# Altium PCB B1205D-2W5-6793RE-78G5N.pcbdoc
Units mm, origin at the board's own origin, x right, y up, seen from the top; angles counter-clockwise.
Board outline 65 x 30 mm, 2 copper layers (Top Layer, Bottom Layer), stack 0.78 mm thick; 15 components, 11 nets, 42 pads, 94 vias.
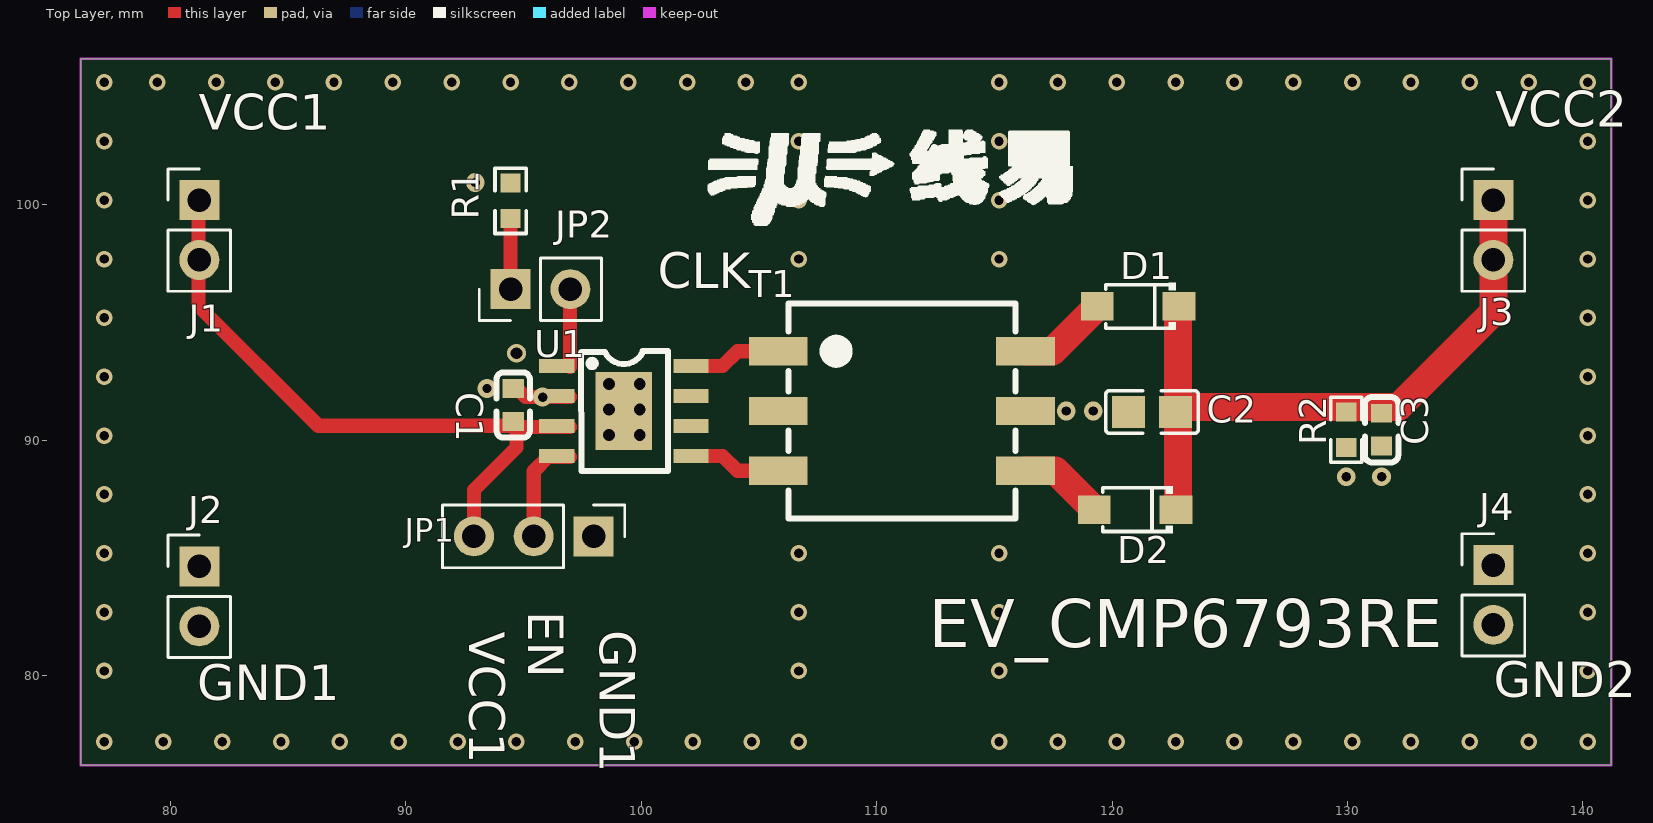
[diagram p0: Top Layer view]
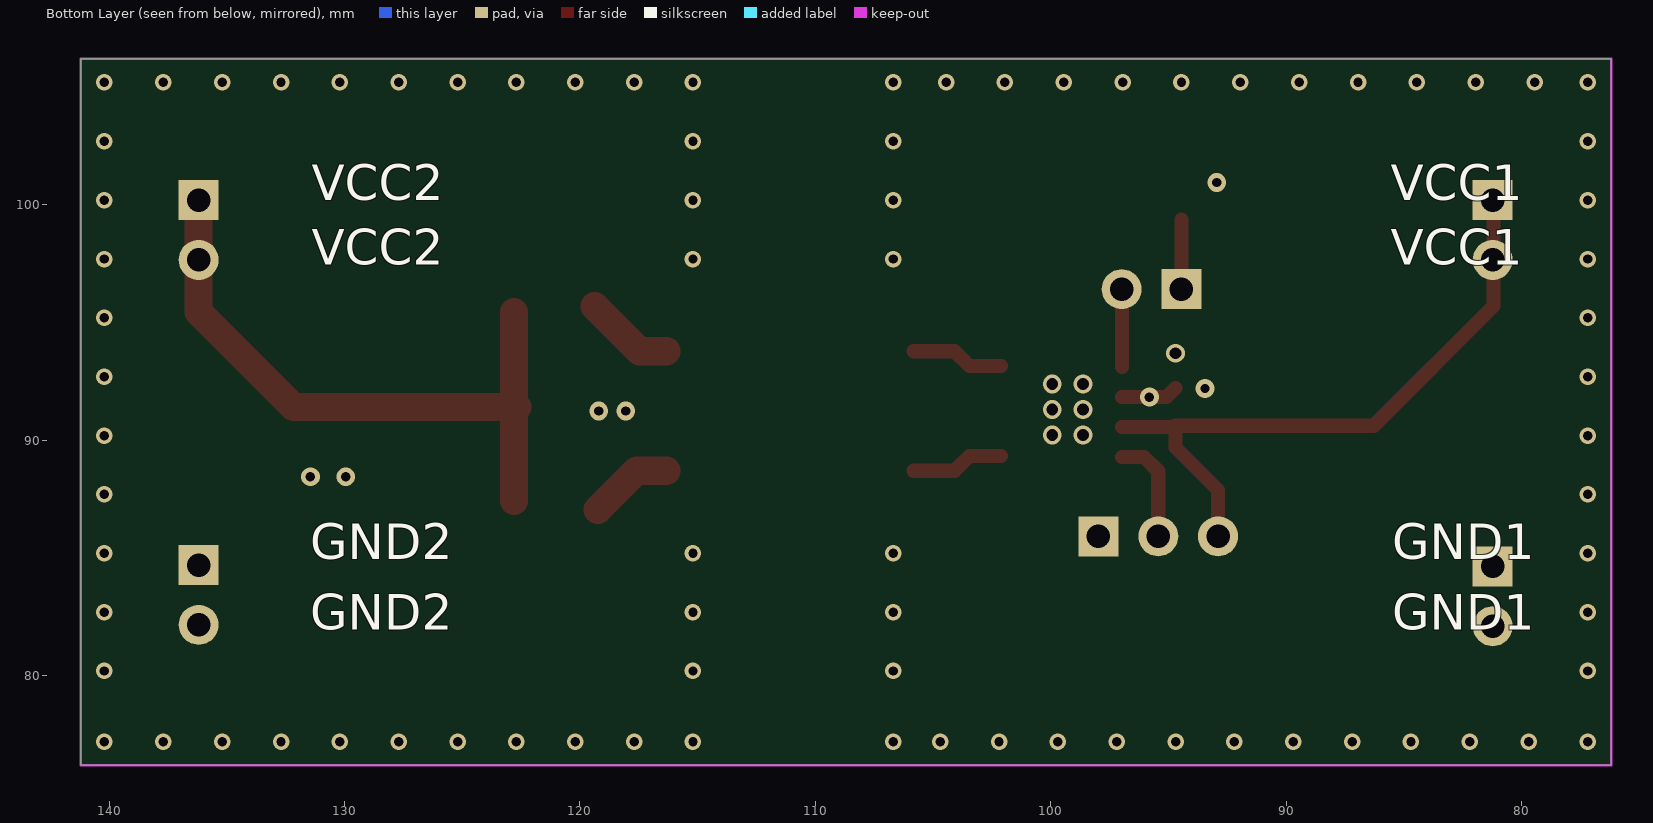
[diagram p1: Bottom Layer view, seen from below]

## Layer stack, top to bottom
Top Solder Mask Layer: solder mask 0.01, Dk 0
Top Layer: signal copper 0.035
dielectric 1: surface 0.71, FR4, Dk 4.5
Bottom Layer: signal copper 0.035
Bottom Solder Mask Layer: solder mask 0.01, Dk 0

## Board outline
76.2,106.2 141.2,106.2 141.2,76.2 76.2,76.2

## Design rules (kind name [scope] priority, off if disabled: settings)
BoardOutlineClearance safeClearance [All] p0: genericclearance=0.254 ignorepadtopadclearanceinfootprint=FALSE except(0: Arc-SplitContinuation Track-SplitContinuation SMDPad-SplitContinuation THPad-SplitContinuation Via-SplitContinuation Fill-SplitContinuation Poly-SplitContinuation Region-SplitContinuation Text-SplitContinuation)
BoardOutlineClearance Plane_innerPlane [All] p0: genericclearance=0.254 ignorepadtopadclearanceinfootprint=FALSE except(0: Arc-SplitContinuation Track-SplitContinuation SMDPad-SplitContinuation THPad-SplitContinuation Via-SplitContinuation Fill-SplitContinuation Poly-SplitContinuation Region-SplitContinuation Text-SplitContinuation)
BoardOutlineClearance Copper_CopperRegion [All] p0: genericclearance=0.254 ignorepadtopadclearanceinfootprint=FALSE except(0: Arc-SplitContinuation Track-SplitContinuation SMDPad-SplitContinuation THPad-SplitContinuation Via-SplitContinuation Fill-SplitContinuation Poly-SplitContinuation Region-SplitContinuation Text-SplitContinuation)
BoardOutlineClearance Copper_CopperRegion1 [All] p0: genericclearance=0.254 ignorepadtopadclearanceinfootprint=FALSE except(0: Arc-SplitContinuation Track-SplitContinuation SMDPad-SplitContinuation THPad-SplitContinuation Via-SplitContinuation Fill-SplitContinuation Poly-SplitContinuation Region-SplitContinuation Text-SplitContinuation)
BoardOutlineClearance Copper_CopperRegion2 [All] p0: genericclearance=0.254 ignorepadtopadclearanceinfootprint=FALSE except(0: Arc-SplitContinuation Track-SplitContinuation SMDPad-SplitContinuation THPad-SplitContinuation Via-SplitContinuation Fill-SplitContinuation Poly-SplitContinuation Region-SplitContinuation Text-SplitContinuation)
BoardOutlineClearance Copper_CopperRegion3 [All] p0: genericclearance=0.254 ignorepadtopadclearanceinfootprint=FALSE except(0: Arc-SplitContinuation Track-SplitContinuation SMDPad-SplitContinuation THPad-SplitContinuation Via-SplitContinuation Fill-SplitContinuation Poly-SplitContinuation Region-SplitContinuation Text-SplitContinuation)
BoardOutlineClearance Copper_CopperRegion4 [All] p0: genericclearance=0.254 ignorepadtopadclearanceinfootprint=FALSE except(0: Arc-SplitContinuation Track-SplitContinuation SMDPad-SplitContinuation THPad-SplitContinuation Via-SplitContinuation Fill-SplitContinuation Poly-SplitContinuation Region-SplitContinuation Text-SplitContinuation)
BoardOutlineClearance otherClearance [All] p0: genericclearance=0.254 ignorepadtopadclearanceinfootprint=FALSE except(0: Arc-SplitContinuation Track-SplitContinuation SMDPad-SplitContinuation THPad-SplitContinuation Via-SplitContinuation Fill-SplitContinuation Poly-SplitContinuation Region-SplitContinuation Text-SplitContinuation)
Clearance safeClearance [All] p1: gap=0.178 ignorepadtopadclearanceinfootprint=FALSE
Clearance Plane_innerPlane [All] p1: gap=0.178 ignorepadtopadclearanceinfootprint=FALSE
Clearance Copper_CopperRegion [All] p1: gap=0.178 ignorepadtopadclearanceinfootprint=FALSE
Clearance Copper_CopperRegion1 [All] p1: gap=0.178 ignorepadtopadclearanceinfootprint=FALSE
Clearance Copper_CopperRegion2 [All] p1: gap=0.178 ignorepadtopadclearanceinfootprint=FALSE
Clearance Copper_CopperRegion3 [All] p1: gap=0.178 ignorepadtopadclearanceinfootprint=FALSE
Clearance Copper_CopperRegion4 [All] p1: gap=0.178 ignorepadtopadclearanceinfootprint=FALSE
Clearance otherClearance [All] p1: gap=0.178 ignorepadtopadclearanceinfootprint=FALSE
DiffPairsRouting differentialPair [All] p1: maxuncoupledlength=10 minlimit=6 maxlimit=Infinity mostfreqgap=6 toplayer_minwidth=5 toplayer_prefwidth=10 toplayer_maxwidth=100 bottomlayer_minwidth=5 bottomlayer_prefwidth=10 bottomlayer_maxwidth=100
PasteMaskExpansion Common [All] p1: expansion=0
PlaneConnect innerPlane [All] p1: planeconnectstyle=Relief reliefexpansion=0.508 reliefentries=4 reliefconductorwidth=0.254 reliefairgap=0.254
PolygonConnect CopperRegion [All] p1: connectstyle=Direct reliefentries=4 reliefconductorwidth=10 polygonreliefangle="90 Angle" airgapwidth=10
PolygonConnect CopperRegion1 [All] p1: connectstyle=Direct reliefentries=4 reliefconductorwidth=10 polygonreliefangle="90 Angle" airgapwidth=10
PolygonConnect CopperRegion2 [All] p1: connectstyle=Direct reliefentries=4 reliefconductorwidth=10 polygonreliefangle="90 Angle" airgapwidth=10
PolygonConnect CopperRegion3 [All] p1: connectstyle=Direct reliefentries=4 reliefconductorwidth=10 polygonreliefangle="90 Angle" airgapwidth=10
PolygonConnect CopperRegion4 [All] p1: connectstyle=Direct reliefentries=4 reliefconductorwidth=10 polygonreliefangle="90 Angle" airgapwidth=10
RoutingVias viaSize [All] p1: viastyle="Through Hole" holewidth=12 minholewidth=11.8 maxholewidth=236.2 width=12 minwidth=11.8 maxwidth=236.2
SolderMaskExpansion Common [All] p1: useseparateexpansions=TRUE expansion=0 expansionbottom=0
Width trackWidth [All] p1: maxlimit=100 minlimit=5 preferedwidth=10

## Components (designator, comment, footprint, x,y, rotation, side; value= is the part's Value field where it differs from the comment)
C1 "" C0603 94.564,91.498 r270 top
C2 "" C0805 121.7,91.2 r0 top
C3 "" C0603 131.45,90.45 r90 top
D1 "" SOD-123FL_L2.7-W1.8-LS3.8-RD 121.107,95.689 r180 top
D2 "" SOD-123FL_L2.7-W1.8-LS3.8-RD 120.98,87.053 r180 top
J1 "" Connector_PinHeader_2.54mm:PinHeader_1x02_P2.54mm_Vertical 81.229,100.2 r0 top
J2 "" Connector_PinHeader_2.54mm:PinHeader_1x02_P2.54mm_Vertical 81.229,84.64 r0 top
J3 "" Connector_PinHeader_2.54mm:PinHeader_1x02_P2.54mm_Vertical 136.2,100.2 r0 top
J4 "" Connector_PinHeader_2.54mm:PinHeader_1x02_P2.54mm_Vertical 136.2,84.7 r0 top
JP1 "Jumper_Jumper_3_Open" Connector_PinHeader_2.54mm:PinHeader_1x03_P2.54mm_Vertical 97.975,85.918 r270 top
JP2 "" Connector_PinHeader_2.54mm:PinHeader_1x02_P2.54mm_Vertical 94.45,96.418 r90 top
R1 "" R0603 94.45,100.168 r270 top
R2 "" R0603 129.95,90.45 r270 top
T1 "" SMD-6_L9.7-W8.9-P2.54-LS12.8-TL 111.074,91.244 r0 top
U1 "" ? 99.263,91.244 r270 top

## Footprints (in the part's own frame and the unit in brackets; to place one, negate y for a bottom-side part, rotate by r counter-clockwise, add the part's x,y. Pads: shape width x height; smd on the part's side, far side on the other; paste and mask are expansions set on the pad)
C0603 [mm]
  rect 0.8x0.9 smd: 1(-0.7,0) 2(0.7,0)
  silkscreen extent -1.39,-0.71 1.39,0.71
C0805 [mm]
  rect 1.41x1.35 smd: 1(-1,0) 2(1,0)
  silkscreen extent -1.96,-0.9 1.96,0.9
Connector_PinHeader_2.54mm:PinHeader_1x02_P2.54mm_Vertical [mm]
  rect 1.7x1.7 hole 1: 1(0,0)
  round 1.7 hole 1: 2(0,-2.54)
  silkscreen extent -1.33,-3.87 1.33,1.33
Connector_PinHeader_2.54mm:PinHeader_1x03_P2.54mm_Vertical [mm]
  rect 1.7x1.7 hole 1: 1(0,0)
  round 1.7 hole 1: 2(0,-2.54) 3(0,-5.08)
  silkscreen extent -1.33,-6.41 1.33,1.33
R0603 [mm]
  rect 0.806x0.864 smd: 1(-0.753,0) 2(0.753,0)
  silkscreen extent -1.39,-0.66 1.39,0.66
SMD-6_L9.7-W8.9-P2.54-LS12.8-TL [mm]
  rect 2.5x1.2 smd: 1(-5.25,2.54) 2(-5.25,0) 3(-5.25,-2.54) 4(5.25,-2.54) 5(5.25,0) 6(5.25,2.54)
  silkscreen extent -4.83,-4.57 4.83,4.57
SOD-123FL_L2.7-W1.8-LS3.8-RD [mm]
  rect 1.4x1.2 smd: 1(-1.735,0) 2(1.735,0)
  silkscreen extent -1.6,-1 1.38,1
? [mm]
  rect 0.6x1.5 smd: 1(-1.905,-2.85) 2(-0.635,-2.85) 3(0.635,-2.85) 4(1.905,-2.85) 5(1.905,2.85) 6(0.635,2.85) 7(-0.635,2.85) 8(-1.905,2.85)
  rect 3.3x2.4 smd: 9(0,0)
  silkscreen extent -2.55,-1.82 2.55,1.88

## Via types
v1: diameter 0.7, hole 0.4, Top Layer to Bottom Layer, 80 vias
v2: diameter 0.8, hole 0.5, Top Layer to Bottom Layer, 7 vias
v3: diameter 0.8, hole 0.4, Top Layer to Bottom Layer, 7 vias

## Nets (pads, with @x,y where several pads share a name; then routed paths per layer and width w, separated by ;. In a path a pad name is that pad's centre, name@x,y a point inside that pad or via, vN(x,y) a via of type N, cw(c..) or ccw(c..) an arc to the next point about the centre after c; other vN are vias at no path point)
$1N3479: JP2.1 R1.2 | length 2.9
  Top Layer w0.6: JP2.1 R1.2@94.45,99.368
$1N3481: T1.3 U1.5 | length 4
  Top Layer w0.599: U1.5 103.454,89.339 104.089,88.704 T1.3
$1N3522: T1.1 U1.8 | length 4
  Top Layer w0.599: U1.8 103.454,93.149 104.089,93.784 T1.1
$1N3537: D1.2 T1.6 | length 3.8
  Top Layer w1.199: T1.6 117.467,93.784 D1.2
$1N3538: D2.2 T1.4 | length 3.6
  Top Layer w1.199: T1.4 117.594,88.704 D2.2
CLK: JP2.2 U1.1 | length 3.3
  Top Layer w0.6: U1.1@96.97,93.105 JP2.2@96.97,96.398
EN: JP1.2 U1.4 | length 4.6
  Top Layer w0.6: JP1.2 95.435,88.685 96.045,89.295 U1.4@96.97,89.295
GND1: C1.1 J2.1 J2.2 JP1.1 R1.1 U1.2 U1.9 | length 2.4
  Top Layer w0.6: C1.1@94.7,92.218 95.083,91.835 v3(95.814,91.835) U1.2@96.97,91.835
  other v1: 77.2,77.2 79.7,77.2 82.2,77.2 84.7,77.2 87.2,77.2 89.7,77.2 92.2,77.2 94.7,77.2 97.2,77.2 99.7,77.2 102.2,77.2 104.7,77.2 106.7,77.2 77.2,80.2 106.7,80.2 77.2,82.7 106.7,82.7 77.2,85.2 106.7,85.2 77.2,87.7 77.2,90.2 77.2,92.7 77.2,95.2 77.2,97.7 106.7,97.7 77.2,100.2 106.7,100.2 77.2,102.7 106.7,102.7 77.2,105.2 79.45,105.2 81.95,105.2 84.45,105.2 86.95,105.2 89.45,105.2 91.95,105.2 94.45,105.2 96.95,105.2 99.45,105.2 101.95,105.2 104.45,105.2 106.7,105.2
  other v2: 98.628,90.228 99.937,90.228 98.628,91.308 99.937,91.308 98.628,92.387 99.937,92.387 94.7,93.7
  other v3: 93.45,92.2 92.95,100.95
GND2: C2.1 C3.1 J4.1 J4.2 R2.2 T1.5
  other v1: 115.2,77.2 117.7,77.2 120.2,77.2 122.7,77.2 125.2,77.2 127.7,77.2 130.2,77.2 132.7,77.2 135.2,77.2 137.7,77.2 140.2,77.2 115.2,80.2 140.2,80.2 115.2,82.7 140.2,82.7 115.2,85.2 140.2,85.2 140.2,87.7 140.2,90.2 140.2,92.7 140.2,95.2 115.2,97.7 140.2,97.7 115.2,100.2 140.2,100.2 115.2,102.7 140.2,102.7 115.2,105.2 117.7,105.2 120.2,105.2 122.7,105.2 125.2,105.2 127.7,105.2 130.2,105.2 132.7,105.2 135.2,105.2 137.7,105.2 140.2,105.2
  other v3: 129.95,88.45 131.45,88.45 118.059,91.244 119.202,91.244
VCC1: C1.2 J1.1 J1.2 JP1.3 U1.3 | length 27.8
  Top Layer w0.6: J1.1@81.2,100.2 81.2,97.66 81.2,95.7 86.282,90.618 94.7,90.618 94.7,89.7 92.895,87.895 JP1.3 ; C1.2@94.753,90.565 U1.3@96.97,90.565
VCC2: C2.2 C3.2 D1.1 D2.1 J3.1 J3.2 R2.1 | length 28
  Top Layer w1.2: C2.2@122.65,91.418 C2.2@122.8,91.418 ; D2.1@122.8,87.418 C2.2@122.8,91.418 ; D1.1@122.8,95.45 C2.2@122.8,91.418 ; J3.1 J3.2 136.2,95.45 132.168,91.418 C2.2@122.8,91.418
pads on no net: T1.2 U1.6 U1.7

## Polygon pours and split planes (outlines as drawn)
GND2 on Top Layer (solid, remove dead copper, pour order 0): 121.2,89.95 118.95,89.95 118.2,90.45 115.2,90.45 115.2,91.95 118.2,91.95 118.95,92.45 121.2,92.45
GND1 on Top Layer (solid, remove dead copper, pour order 2): 107.2,76.2 76.2,76.2 76.2,106.2 107.2,106.2
GND1 on Bottom Layer (solid, remove dead copper, pour order 6): 107.2,76.2 76.2,76.2 76.2,106.2 107.2,106.2
GND2 on Top Layer (solid, remove dead copper, pour order 4): 141.2,76.2 114.7,76.2 114.7,85.95 123.95,85.95 123.95,96.7 114.7,96.7 114.7,106.2 141.2,106.2
GND2 on Bottom Layer (solid, remove dead copper, pour order 8): 141.2,76.2 114.7,76.2 114.7,106.2 141.2,106.2

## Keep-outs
Board Outline Layer:
  the board outline again, w0.1

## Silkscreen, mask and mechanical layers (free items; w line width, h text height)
Top Silkscreen Layer:
  drawing of 9 lines, arcs and shapes, not listed
  text "VCC2" at 136.283,103.327 h1.5
  text "VCC1" at 81.196,103.2 h1.5
  text "CLK" at 100.7,96.45 h1.5
  text "EN" at 95.199,82.735 h1.5 r270
  text "GND1" at 98.247,81.939 h1.5 r270
  text "VCC1" at 92.7,81.875 h1.5 r270
  text "EV_CMP6793RE" at 112.217,81.211 h2.03
  text "GND2" at 136.22,79.077 h1.5
  text "GND1" at 81.132,78.95 h1.5
Bottom Silkscreen Layer:
  text "VCC1" at 85.557,100.2 h1.5
  text "VCC2" at 131.386,100.2 h1.5
  text "VCC1" at 85.557,97.45 h1.5
  text "VCC2" at 131.386,97.45 h1.5
  text "GND1" at 85.494,84.95 h1.5
  text "GND2" at 131.45,84.95 h1.5
  text "GND1" at 85.494,81.95 h1.5
  text "GND2" at 131.45,81.95 h1.5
